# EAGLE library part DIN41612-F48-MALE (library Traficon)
Male Eurocard connector PCB mounting 90° Manufacturer: AMP Productnumber: 2-164045-8
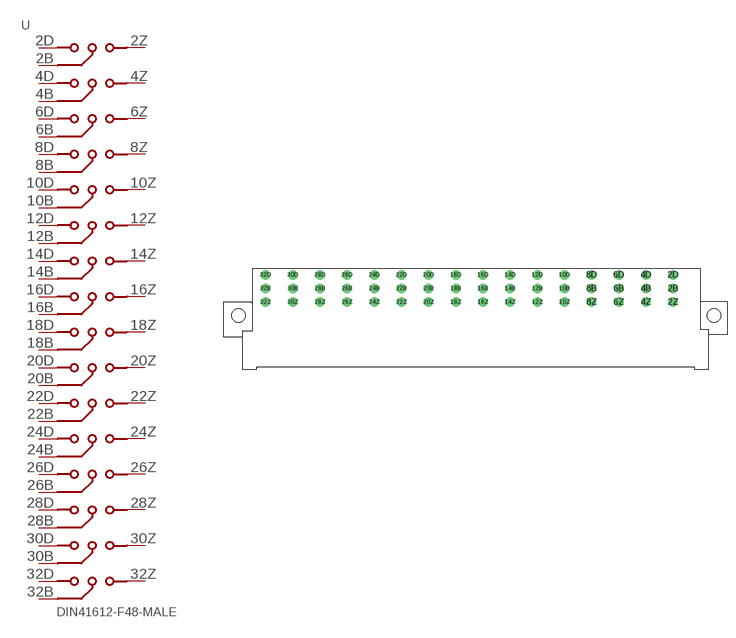
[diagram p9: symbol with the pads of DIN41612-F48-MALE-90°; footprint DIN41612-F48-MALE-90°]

Designator prefix -

## DIN41612-F48-MALE  [DIN41612-F48-MALE-90°]
2B  2B
2D  2D
2Z  2Z
4B  4B
4D  4D
4Z  4Z
6B  6B
6D  6D
6Z  6Z
8B  8B
8D  8D
8Z  8Z
10B  10B
10D  10D
10Z  10Z
12B  12B
12D  12D
12Z  12Z
14B  14B
14D  14D
14Z  14Z
16B  16B
16D  16D
16Z  16Z
18B  18B
18D  18D
18Z  18Z
20B  20B
20D  20D
20Z  20Z
22B  22B
22D  22D
22Z  22Z
24B  24B
24D  24D
24Z  24Z
26B  26B
26D  26D
26Z  26Z
28B  28B
28D  28D
28Z  28Z
30B  30B
30D  30D
30Z  30Z
32B  32B
32D  32D
32Z  32Z

## Footprint DIN41612-F48-MALE-90° (pad centres in mm)
drill 1.016 pad 1.778 round: 2B 38.1,0; 2D 38.1,2.54; 2Z 38.1,-2.54; 4B 33.02,0; 4D 33.02,2.54; 4Z 33.02,-2.54; 6B 27.94,0; 6D 27.94,2.54; 6Z 27.94,-2.54; 8B 22.86,0; 8D 22.86,2.54; 8Z 22.86,-2.54; 10B 17.78,0; 10D 17.78,2.54; 10Z 17.78,-2.54; 12B 12.7,0; 12D 12.7,2.54; 12Z 12.7,-2.54; 14B 7.62,0; 14D 7.62,2.54; 14Z 7.62,-2.54; 16B 2.54,0; 16D 2.54,2.54; 16Z 2.54,-2.54; 18B -2.54,0; 18D -2.54,2.54; 18Z -2.54,-2.54; 20B -7.62,0; 20D -7.62,2.54; 20Z -7.62,-2.54; 22B -12.7,0; 22D -12.7,2.54; 22Z -12.7,-2.54; 24B -17.78,0; 24D -17.78,2.54; 24Z -17.78,-2.54; 26B -22.86,0; 26D -22.86,2.54; 26Z -22.86,-2.54; 28B -27.94,0; 28D -27.94,2.54; 28Z -27.94,-2.54; 30B -33.02,0; 30D -33.02,2.54; 30Z -33.02,-2.54; 32B -38.1,0; 32D -38.1,2.54; 32Z -38.1,-2.54
hole 2.54 at -43.18,-5.08
hole 2.54 at 45.72,-5.08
